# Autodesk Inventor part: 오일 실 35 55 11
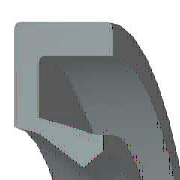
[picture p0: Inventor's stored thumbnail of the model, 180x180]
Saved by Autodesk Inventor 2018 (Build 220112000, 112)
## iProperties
IsCustomPart: 1
Created: 2012-02
Part Number: 오일 실 35 55 11
Material: 고무
Description: 오일 실 - 비스프링, 조립 GA
Document SubType Name: Modeling
Standard: JIS B 2402
Designer: mdu-01
Standards Organization: JIS
Language: ko-KR
Size Designation: 35 55 11 A
Categories: <MemberInstance><Categories><Category DisplayName="샤프트 부품" InternalName="7f7aeb1f-a693-4053-b835-cee3144e0d98" Mnemonic="SHFT"><Category DisplayName="실링" Intern
Density: 0.93 g/cm^3
Appearance: Rubber-Black
Author: mdu-01
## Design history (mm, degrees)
body "Solid1"
revolve "회전1" stored, may be unused: angle "d27" = 360 deg
fillet "모깎기1" dims "d28" = 0.55 (= 0.05 x b)
sketch "스케치2"
  geometry: L1 (20.786, -8.25)-(21.786, -11); L2 (19.452, -7.563)-(20.786, -8.25); L3 (17.5, -3.025)-(19.452, -7.563); L4 (19.038, -1.65)-(17.5, -3.025); L5 (23.5, -9.625)-(19.038, -1.65); L6 (23.5, -0.55)-(23.5, -9.625); L7 (25.5, -0.55)-(23.5, -0.55); L8 (25.5, 0)-(25.5, -0.55); L9 (27.5, 0)-(25.5, 0); L10 (27.5, -11)-(27.5, 0); L11 (21.786, -11)-(27.5, -11); L12 (0, -9.6)-(0, 1.6) reference; L13 (28, 0)-(14, 0) reference
  constraints: 22 end point, 3 horizontal, 3 vertical
  dimensions: "d2" = 11 distance of L10.start L9.start (= b); "d4" = 2 distance of L9.start L8.start (= 0.1 x dd - 0.1 x Diam); "d6" = 0.55 distance of L8.start L7.start (= 0.05 x b); "d8" = 1.53846 horizontal distance of L4.start L3.start (= 0.0769231 x dd - 0.0769231 x Diam); "d10" = 1.375 vertical distance of L5.start L10.start (= 0.125 x b); "d12" = 2 distance of L7.start L6.start (= 0.1 x dd - 0.1 x Diam); "d14" = 1.1 vertical distance of L4.start L6.start (= 0.1 x b); "d16" = 5.71429 distance of L1.end L10.start (= 0.285714 x dd - 0.285714 x Diam); "d18" = 1 horizontal distance of L1.start L1.end (= 0.05 x dd - 0.05 x Diam); "d20" = 1.375 vertical distance of L4.start L3.start (= 0.125 x b); "d22" = 2.75 vertical distance of L1.start L1.end (= 0.25 x b); "d24" = 1.33333 horizontal distance of L2.start L1.start (= 0.0666667 x dd - 0.0666667 x Diam); "d26" = 0.6875 vertical distance of L2.start L1.start (= 0.0625 x b); "d29" = 0 distance between parallel lines of L13 L9; "d30" = 17.5 distance from line of L3.start L12 (= 0.5 x Diam); "d31" = 27.5 distance between parallel lines of L12 L10 (= 0.5 x dd)
other parameters: "dd" = 55 [user parameter; used in 7 equation terms], "Diam" = 35 [user parameter; used in 7 equation terms], "b" = 11 [user parameter; used in 8 equation terms], "d1" = 8 (derived), "d3" = 2 (derived), "d5" = 0.4 (derived), "d7" = 1.53846 (derived), "d9" = 1 (derived), "d11" = 2 (derived), "d13" = 0.8 (derived), "d15" = 5.71429 (derived), "d17" = 1 (derived), "d19" = 1 (derived), "d21" = 2 (derived), "d23" = 1.33333 (derived), "d25" = 0.5 (derived), "d32" = 0
